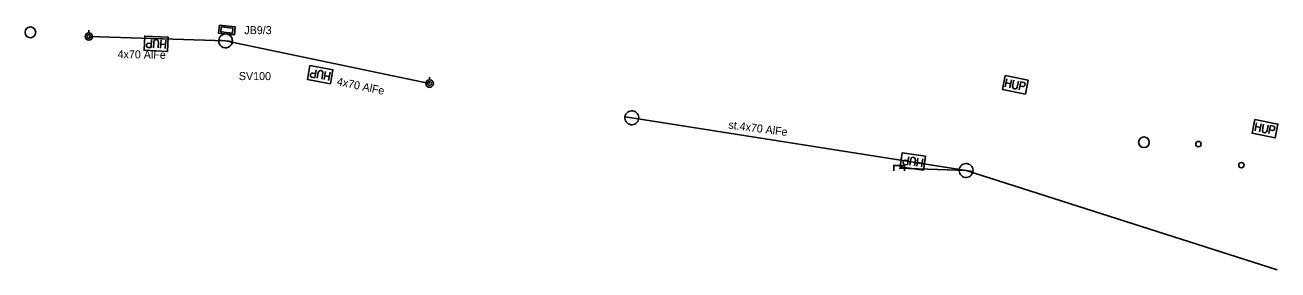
# Model space of a CAD drawing. Extents: x -762500 to -761250, y -1152983 to -1152297.
# Drawn here: x -761476.6 to -761359.2, y -1152551.9 to -1152529 of the extents above; entities that cross this region are included whole.
import ezdxf

# ---------------------------------------------------------------- set-up
doc = ezdxf.new("R2010")
doc.units = 0
for name, color, linetype in [('Vrstva 1', 7, 'Continuous'), ('Vrstva 2', 7, 'Continuous'), ('Vrstva 9', 7, 'Continuous')]:
    doc.layers.add(name, color=color, linetype=linetype)

msp = doc.modelspace()

# ---------------------------------------------------------------- linework, layer by layer
at = {"layer": 'Vrstva 1'}
for p, q in [((-761470.65, -1152529.74), (-761470.65, -1152529.49)), ((-761457.184, -1152530.572), (-761458.476, -1152530.428)), ((-761438.71, -1152534.15), (-761438.71, -1152533.9)), ((-761419.118, -1152537.801), (-761420.402, -1152537.599)), ((-761387.788, -1152542.731), (-761389.072, -1152542.529))]:
    msp.add_line(p, q, dxfattribs=at)
for points in [[(-761458.415, -1152529.024), (-761456.925, -1152529.195), (-761457.011, -1152529.94), (-761458.501, -1152529.769)], [(-761458.234, -1152529.195), (-761457.141, -1152529.321), (-761457.192, -1152529.768), (-761458.285, -1152529.642)]]:
    msp.add_lwpolyline(points, close=True, dxfattribs=at)
for points in [[(-761470.65, -1152530.09), (-761457.83, -1152530.5)], [(-761438.71, -1152534.5), (-761457.83, -1152530.5)], [(-761388.43, -1152542.63), (-761419.76, -1152537.7)], [(-761395.21, -1152542.66), (-761395.21, -1152542.16), (-761394.21, -1152542.16), (-761394.21, -1152542.66)], [(-761388.43, -1152542.63), (-761394.71, -1152542.41)], [(-761388.43, -1152542.63), (-761359.26, -1152551.93)]]:
    msp.add_lwpolyline(points, dxfattribs=at)
for centre, radius in [((-761470.65, -1152530.09), 0.35), ((-761470.65, -1152530.09), 0.175), ((-761438.71, -1152534.5), 0.35), ((-761438.71, -1152534.5), 0.175)]:
    msp.add_circle(centre, radius, dxfattribs=at)
for centre, start, end in [((-761457.83, -1152530.5), 173.60742, 353.60742), ((-761457.83, -1152530.5), 353.60742, 173.60742), ((-761419.76, -1152537.7), 171.05728, 351.05728), ((-761419.76, -1152537.7), 351.05728, 171.05728), ((-761388.43, -1152542.63), 171.05728, 351.05728), ((-761388.43, -1152542.63), 351.05728, 171.05728)]:
    msp.add_arc(centre, 0.65, start, end, dxfattribs=at)
at = {"layer": 'Vrstva 9'}
for points in [[(-761463.279, -1152531.485), (-761465.476, -1152531.372), (-761465.409, -1152530.054), (-761463.211, -1152530.166), (-761463.279, -1152531.485)], [(-761464.803, -1152531.131), (-761465.089, -1152531.116), (-761465.179, -1152531.075), (-761465.21, -1152531.037), (-761465.237, -1152530.964), (-761465.231, -1152530.854), (-761465.197, -1152530.782), (-761465.162, -1152530.749), (-761465.068, -1152530.717), (-761464.783, -1152530.732)], [(-761464.764, -1152530.362), (-761464.803, -1152531.131)], [(-761464.144, -1152531.165), (-761464.116, -1152530.614), (-761464.141, -1152530.504), (-761464.205, -1152530.428), (-761464.296, -1152530.386), (-761464.359, -1152530.383), (-761464.454, -1152530.415), (-761464.521, -1152530.485), (-761464.557, -1152530.591), (-761464.585, -1152531.142)], [(-761463.887, -1152530.407), (-761463.926, -1152531.176)], [(-761463.466, -1152530.836), (-761463.908, -1152530.814)], [(-761463.485, -1152531.199), (-761463.445, -1152530.43)], [(-761448.007, -1152534.507), (-761450.171, -1152534.109), (-761449.932, -1152532.811), (-761447.768, -1152533.209), (-761448.007, -1152534.507)], [(-761449.472, -1152533.958), (-761449.753, -1152533.906), (-761449.837, -1152533.853), (-761449.863, -1152533.812), (-761449.88, -1152533.735), (-761449.861, -1152533.627), (-761449.817, -1152533.561), (-761449.778, -1152533.533), (-761449.681, -1152533.513), (-761449.4, -1152533.565)], [(-761449.333, -1152533.201), (-761449.472, -1152533.958)], [(-761448.823, -1152534.078), (-761448.723, -1152533.535), (-761448.734, -1152533.423), (-761448.788, -1152533.339), (-761448.872, -1152533.286), (-761448.934, -1152533.274), (-761449.032, -1152533.294), (-761449.108, -1152533.354), (-761449.158, -1152533.455), (-761449.258, -1152533.997)], [(-761448.469, -1152533.36), (-761448.609, -1152534.117)], [(-761448.108, -1152533.84), (-761448.543, -1152533.76)], [(-761448.174, -1152534.197), (-761448.034, -1152533.44)], [(-761384.766, -1152533.748), (-761382.61, -1152534.185), (-761382.872, -1152535.478), (-761385.028, -1152535.042), (-761384.766, -1152533.748)], [(-761384.605, -1152534.061), (-761384.758, -1152534.816)], [(-761384.325, -1152534.904), (-761384.172, -1152534.149)], [(-761383.958, -1152534.192), (-761384.068, -1152534.733), (-761384.059, -1152534.845), (-761384.007, -1152534.93), (-761383.923, -1152534.985), (-761383.861, -1152534.997), (-761383.763, -1152534.98), (-761383.686, -1152534.921), (-761383.635, -1152534.821), (-761383.525, -1152534.28)], [(-761383.464, -1152535.078), (-761383.311, -1152534.323)], [(-761383.311, -1152534.323), (-761383.031, -1152534.38), (-761382.948, -1152534.434), (-761382.923, -1152534.476), (-761382.907, -1152534.553), (-761382.929, -1152534.661), (-761382.974, -1152534.726), (-761383.013, -1152534.754), (-761383.11, -1152534.772), (-761383.391, -1152534.715)], [(-761384.677, -1152534.417), (-761384.244, -1152534.505)], [(-761361.356, -1152537.848), (-761359.2, -1152538.285), (-761359.462, -1152539.578), (-761361.618, -1152539.142), (-761361.356, -1152537.848)], [(-761361.195, -1152538.161), (-761361.348, -1152538.916)], [(-761361.267, -1152538.517), (-761360.834, -1152538.605)], [(-761360.915, -1152539.004), (-761360.762, -1152538.249)], [(-761360.548, -1152538.292), (-761360.658, -1152538.833), (-761360.649, -1152538.945), (-761360.597, -1152539.03), (-761360.513, -1152539.085), (-761360.451, -1152539.097), (-761360.353, -1152539.08), (-761360.276, -1152539.021), (-761360.225, -1152538.921), (-761360.115, -1152538.38)], [(-761360.054, -1152539.178), (-761359.901, -1152538.423)], [(-761359.901, -1152538.423), (-761359.621, -1152538.48), (-761359.538, -1152538.534), (-761359.513, -1152538.576), (-761359.497, -1152538.653), (-761359.519, -1152538.761), (-761359.564, -1152538.826), (-761359.603, -1152538.854), (-761359.7, -1152538.872), (-761359.981, -1152538.815)], [(-761392.434, -1152542.596), (-761394.61, -1152542.276), (-761394.418, -1152540.97), (-761392.242, -1152541.29), (-761392.434, -1152542.596)], [(-761393.805, -1152541.338), (-761393.917, -1152542.1)], [(-761393.917, -1152542.1), (-761394.2, -1152542.058), (-761394.286, -1152542.008), (-761394.313, -1152541.968), (-761394.334, -1152541.892), (-761394.318, -1152541.783), (-761394.276, -1152541.715), (-761394.239, -1152541.686), (-761394.142, -1152541.662), (-761393.859, -1152541.704)], [(-761393.264, -1152542.196), (-761393.184, -1152541.65), (-761393.199, -1152541.538), (-761393.256, -1152541.456), (-761393.342, -1152541.406), (-761393.405, -1152541.397), (-761393.502, -1152541.42), (-761393.575, -1152541.483), (-761393.621, -1152541.585), (-761393.702, -1152542.132)], [(-761392.937, -1152541.466), (-761393.049, -1152542.228)], [(-761392.559, -1152541.933), (-761392.996, -1152541.868)], [(-761392.611, -1152542.292), (-761392.499, -1152541.53)]]:
    msp.add_lwpolyline(points, dxfattribs=at)
for centre, radius in [((-761476.13, -1152529.7), 0.5), ((-761371.76, -1152539.99), 0.5), ((-761366.65, -1152540.16), 0.25), ((-761362.63, -1152542.13), 0.25)]:
    msp.add_circle(centre, radius, dxfattribs=at)

# ---------------------------------------------------------------- texts
at = {"layer": 'Vrstva 2'}
for s, p in [('JB9/3', (-761456.08, -1152529.87)), ('SV100', (-761456.59, -1152534.17))]:
    msp.add_text(s, height=0.75, dxfattribs=at).set_placement(p)
for s, rotation, p in [('4x70 AlFe', 359.25692, (-761467.96, -1152532.12)), ('4x70 AlFe', 348.18385, (-761447.45, -1152534.63)), ('st.4x70 AlFe', 352.71059, (-761410.74, -1152538.7))]:
    msp.add_text(s, height=0.75, rotation=rotation, dxfattribs=at).set_placement(p)

doc.saveas('drawing.dxf')
